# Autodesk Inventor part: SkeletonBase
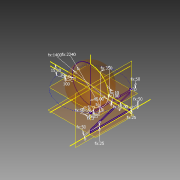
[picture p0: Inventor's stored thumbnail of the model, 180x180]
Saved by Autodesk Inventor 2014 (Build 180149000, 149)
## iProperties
Shininess: 64.0
Angle Display Precision: 2
Document Length Units: 11269
Document Angle Units: 11279
Document Time Units: 11290
Document Mass Units: 11283
Document Length Units Precision: 3
Document Angle Units Precision: 2
Compacted: True
Created: 2002-07
Part Number: SkeletonBase
Document SubType Name: Modeling
Designer: t_munrn
Density: 1 g/cm^3
Material: Generic
Appearance: Default
Density: 0.0
Volumn: 0.0
Area: 0.0
PropertySet Name: Model Information
Control State: 0
Master: False
Checked Out: False
TubeWall: 3.000 mm
TubeSize: 50.000 mm
SphereDia: 1400.000 mm
d: 1400.000 mm
t1: 1400.000 mm
SphereDiameter: 1400.000 mm
TubeThickness: 3.000 mm
Author: t_munrn
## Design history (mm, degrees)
sketch "SPHERE SKETCH"
  geometry: L1 (0, 700)-(0, -700); A1 r 700 centre (0, 0) between (0, -700) and (0, 700); 1 further point
  constraints: 2 end point, 2 point on circle, 1 centre point, 1 coincident, 1 midpoint, 1 vertical
  dimensions: "d0" = 1400 diameter of A1 (= SphereDiameter)
feature "SPHERE" sketch "SPHERE SKETCH" dims angle "d1" = 90 deg
sketch "CIRC STRAP SKETCH"
  geometry: L1 (689.089, -132.877)-(663.207, -229.47); L2 (663.207, -229.47)-(672.866, -232.058); L3 (672.866, -232.058)-(698.748, -135.465); L4 (698.748, -135.465)-(689.089, -132.877); L5 (0, 0)-(676.148, -181.173); L6 (-1568, 0)-(1568, 0) reference; L7 (0, -1185.408)-(0, 1014.235) reference; L8 (-689.089, -132.877)-(-663.207, -229.47); L9 (-663.207, -229.47)-(-672.866, -232.058); L10 (-672.866, -232.058)-(-698.748, -135.465); L11 (-698.748, -135.465)-(-689.089, -132.877); L12 (0, 0)-(-676.148, -181.173); C1 r 700 at (0, 0) reference
  constraints: 20 end point, 4 parallel, 4 perpendicular, 2 midpoint, 2 tangent
  dimensions: "d2" = 15 deg angle of L5 L6; "d3" = 100 distance of L2.end L3.end; "d4" = 10 distance of L3.end L1.start; "d25" = 10 distance of L10.end L8.start (= d4); "d26" = 100 distance of L9.end L10.end (= d3); "d27" = 15 deg angle of L6 L12 (= d2)
feature "STRAP SURFACE" dims angle "d28" = 180 deg
workplane "Work Plane - Strap Centerline"
workplane "Work Plane - TOP of Frame"
workplane "Work Plane - BOTT of Frame"
sketch "VERTICAL LEGS SKETCH" dims "d10" = 2240 (= 1.6 x SphereDiameter)
  geometry: L1 (1448.108, -766.96)-(1488.108, -766.96); L2 (1493.108, -771.96)-(1493.108, -811.96); L3 (1488.108, -816.96)-(1448.108, -816.96); L4 (1443.108, -811.96)-(1443.108, -771.96); L5 (1490.108, -771.96)-(1490.108, -811.96); L6 (1488.108, -813.96)-(1448.108, -813.96); L7 (1446.108, -811.96)-(1446.108, -771.96); L8 (1448.108, -769.96)-(1488.108, -769.96); L9 (1488.108, -771.96)-(1448.108, -811.96); L10 (676.148, 0)-(1468.108, -791.96); L11 (676.148, -1568)-(676.148, 1568) reference; L12 (2244.148, 0)-(-891.852, 0) reference; L13 (1448.108, 766.96)-(1488.108, 766.96); L14 (1488.108, 816.96)-(1448.108, 816.96); L15 (1443.108, 811.96)-(1443.108, 771.96); L16 (1448.108, 769.96)-(1488.108, 769.96); L17 (1446.108, 811.96)-(1446.108, 771.96); L18 (1488.108, 771.96)-(1448.108, 811.96); L19 (1488.108, 813.96)-(1448.108, 813.96); L20 (1493.108, 771.96)-(1493.108, 811.96); L21 (1490.108, 771.96)-(1490.108, 811.96); A1 r 5 centre (1448.108, -771.96) between (1448.108, -766.96) and (1443.108, -771.96); A2 r 5 centre (1488.108, -771.96) between (1493.108, -771.96) and (1488.108, -766.96); A3 r 5 centre (1488.108, -811.96) between (1488.108, -816.96) and (1493.108, -811.96); A4 r 5 centre (1448.108, -811.96) between (1443.108, -811.96) and (1448.108, -816.96); A5 r 2 centre (1488.108, -771.96) between (1490.108, -771.96) and (1488.108, -769.96); A6 r 2 centre (1488.108, -811.96) between (1488.108, -813.96) and (1490.108, -811.96); A7 r 2 centre (1448.108, -811.96) between (1446.108, -811.96) and (1448.108, -813.96); A8 r 2 centre (1448.108, -771.96) between (1448.108, -769.96) and (1446.108, -771.96); A9 r 5 centre (1448.108, 771.96) between (1443.108, 771.96) and (1448.108, 766.96); A10 r 2 centre (1448.108, 771.96) between (1446.108, 771.96) and (1448.108, 769.96); A11 r 2 centre (1448.108, 811.96) between (1448.108, 813.96) and (1446.108, 811.96); A12 r 5 centre (1448.108, 811.96) between (1448.108, 816.96) and (1443.108, 811.96); A13 r 2 centre (1488.108, 771.96) between (1488.108, 769.96) and (1490.108, 771.96); A14 r 5 centre (1488.108, 771.96) between (1488.108, 766.96) and (1493.108, 771.96); A15 r 2 centre (1488.108, 811.96) between (1490.108, 811.96) and (1488.108, 813.96); A16 r 5 centre (1488.108, 811.96) between (1493.108, 811.96) and (1488.108, 816.96); 6 further points
  constraints: 38 end point, 32 point on circle, 23 symmetric about line, 16 centre point, 8 point on line, 8 tangent, 4 parallel, 3 equal radius, 3 perpendicular, 1 coincident, 1 horizontal, 1 midpoint, 27 other
  dimensions: "d8" = 5 radius of A1; "d9" = 3 distance between parallel lines of L4 L7 (= TubeThickness); "d30" = 45 deg angle of L12 L10; "d34" = 50 distance between parallel lines of L1 L3 (= TubeSize)
workplane "Work Plane - Frame Inner Surface"
sketch "FRAME SKETCH"
  geometry: L1 (5, -725)-(1538.919, -725); L2 (1538.919, -725)-(1538.919, -675); L3 (1538.919, -675)-(5, -675); L4 (5, -675)-(5, -725); L5 (5, -597.437)-(1538.919, -100); L6 (5, -650)-(1538.919, -152.563); L7 (5, -597.437)-(5, -650); L8 (1538.919, -100)-(1538.919, -152.563); L9 (1538.919, -75)-(1538.919, -100); L10 (5, -650)-(5, -675); L11 (-796.04, -750)-(2339.96, -750) reference; L12 (5, -75)-(1538.919, -75); L13 (1538.919, -75)-(1538.919, -25); L14 (1538.919, -25)-(5, -25); L15 (5, -25)-(5, -75); 3 further points
  constraints: 28 end point, 7 parallel, 4 collinear, 2 perpendicular, 2 point on line
  dimensions: "d37" = 50 distance of L1.end L2.end (= TubeSize); "d38" = 50 distance between parallel lines of L6 L5 (= TubeSize); "d39" = 25 distance from line of L3 L6.start (= 0.5 x TubeSize); "d43" = 25 distance between parallel lines of L11 L1 (= 0.5 x TubeSize); "d44" = 50 distance of L9.start L13.end (= TubeSize); "d45" = 25 distance from line of L14 point (5, 0) (= 0.5 x TubeSize)
sketch "SUPPORTS SKETCH"
  geometry: L1 (376.96, -25)-(416.96, -25); L2 (421.96, -30)-(421.96, -70); L3 (416.96, -75)-(376.96, -75); L4 (371.96, -70)-(371.96, -30); L5 (376.96, -28)-(416.96, -28); L6 (418.96, -30)-(418.96, -70); L7 (416.96, -72)-(376.96, -72); L8 (374.96, -70)-(374.96, -30); L9 (771.96, 146.173)-(771.96, 114.793); L10 (1166.96, -28)-(1126.96, -28); L11 (1168.96, -70)-(1168.96, -30); L12 (1171.96, -70)-(1171.96, -30); L13 (1126.96, -72)-(1166.96, -72); L14 (1126.96, -75)-(1166.96, -75); L15 (1166.96, -25)-(1126.96, -25); L16 (1124.96, -30)-(1124.96, -70); L17 (1121.96, -30)-(1121.96, -70); L18 (5, -75)-(1538.919, -75) reference; L19 (1538.919, -25)-(5, -25) reference; A1 r 5 centre (376.96, -30) between (376.96, -25) and (371.96, -30); A2 r 5 centre (416.96, -30) between (421.96, -30) and (416.96, -25); A3 r 5 centre (416.96, -70) between (416.96, -75) and (421.96, -70); A4 r 5 centre (376.96, -70) between (371.96, -70) and (376.96, -75); A5 r 2 centre (376.96, -30) between (376.96, -28) and (374.96, -30); A6 r 2 centre (416.96, -30) between (418.96, -30) and (416.96, -28); A7 r 2 centre (416.96, -70) between (416.96, -72) and (418.96, -70); A8 r 2 centre (376.96, -70) between (374.96, -70) and (376.96, -72); A9 r 2 centre (1166.96, -30) between (1168.96, -30) and (1166.96, -28); A10 r 5 centre (1166.96, -30) between (1171.96, -30) and (1166.96, -25); A11 r 2 centre (1166.96, -70) between (1166.96, -72) and (1168.96, -70); A12 r 5 centre (1166.96, -70) between (1166.96, -75) and (1171.96, -70); A13 r 2 centre (1126.96, -70) between (1124.96, -70) and (1126.96, -72); A14 r 5 centre (1126.96, -70) between (1121.96, -70) and (1126.96, -75); A15 r 2 centre (1126.96, -30) between (1126.96, -28) and (1124.96, -30); A16 r 5 centre (1126.96, -30) between (1126.96, -25) and (1121.96, -30); 4 further points
  constraints: 34 end point, 32 point on circle, 22 symmetric about line, 16 centre point, 8 point on line, 8 tangent, 5 parallel, 3 equal radius, 3 perpendicular, 2 collinear, 1 horizontal, 23 other
  dimensions: "d40" = 350 distance from line of L9.start L2 (= 0.25 x SphereDiameter); "d41" = 5 radius of A1; "d42" = 3 distance between parallel lines of L4 L8 (= TubeThickness)
body "Srf1"
body "Srf2"
other parameters: "d6" = 35, "SphereDiameter" = 1400 [user parameter; used in 3 equation terms], "TubeThickness" = 3 [user parameter; used in 2 equation terms], "TubeSize" = 50 [user parameter; used in 7 equation terms]
